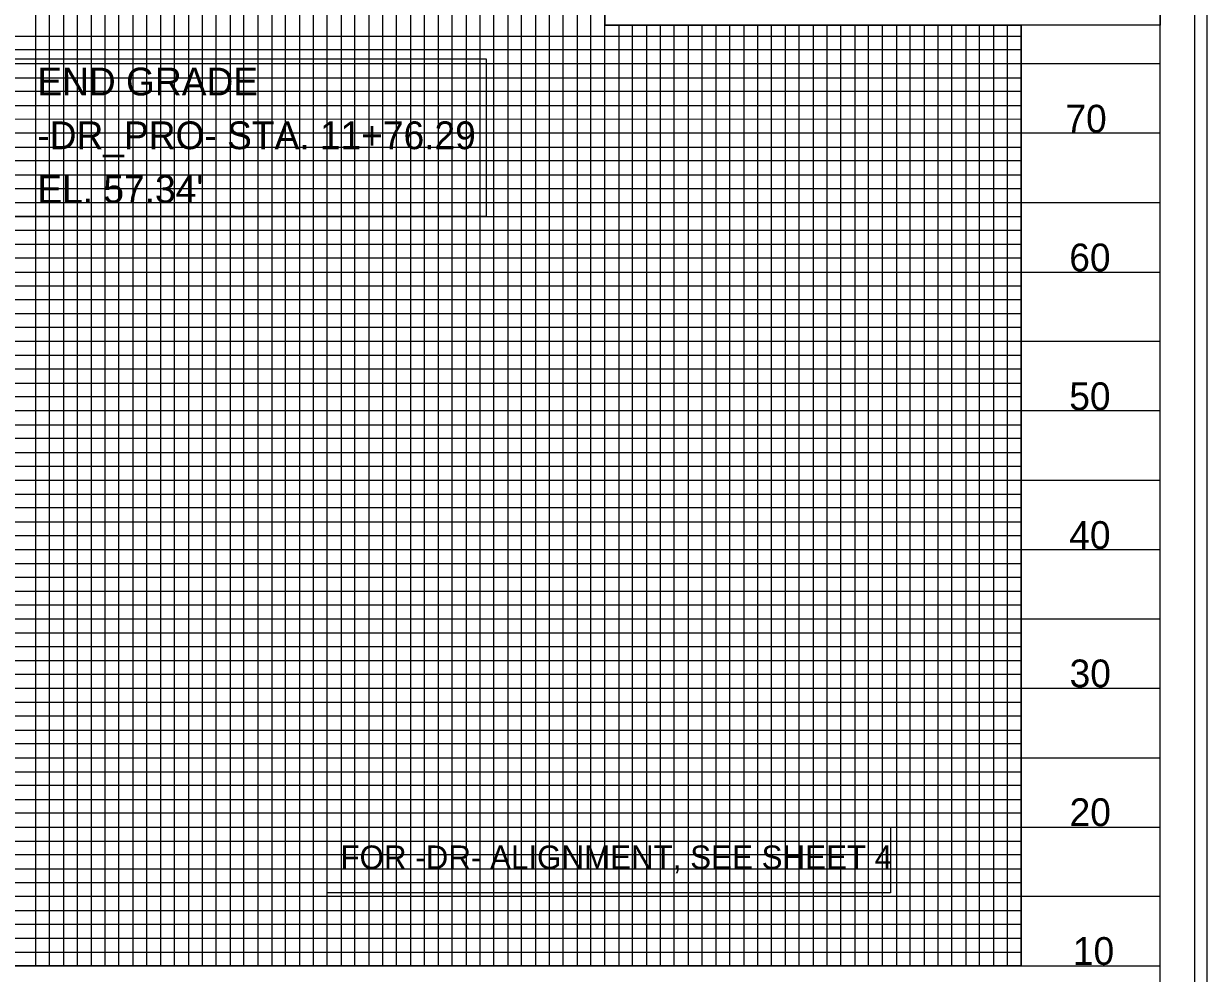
# Model space of a CAD drawing. Extents: x 1019474 to 1021158, y 503201 to 504732.
# Drawn here: x 1020731.9 to 1021158.2, y 503773.1 to 504115.2 of the extents above; entities that cross this region are included whole.
import ezdxf

# ---------------------------------------------------------------- set-up
doc = ezdxf.new("R2010")
doc.units = 0
for name, color, linetype in [('Exist Vertical Profile Vertical Axis Label', 7, 'Continuous'), ('Prop Grid Mask', 7, 'Continuous'), ('Prop Horizontal Alignment Station Label', 7, 'Continuous'), ('Prop Vertical Profile Grade Label', 7, 'Continuous'), ('Scratch_Level_0', 7, 'Continuous'), ('Sheet Layout Profile Border Port 1', 7, 'Continuous'), ('Sheet Layout Profile Border Port 2', 7, 'Continuous'), ('Sheet Plot Border Inside CELL', 7, 'Continuous'), ('Sheet Plot Border Outside CELL', 7, 'Continuous'), ('Sheet Profile CELL', 7, 'Continuous'), ('Sheet Profile Grid Major CELL', 7, 'Continuous'), ('Sheet Profile Grid Middle CELL', 7, 'Continuous'), ('Sheet Profile Grid Minor CELL', 7, 'Continuous'), ('Sheet Sticker Exception Certification CELL', 7, 'Continuous')]:
    doc.layers.add(name, color=color, linetype=linetype)

msp = doc.modelspace()

# ---------------------------------------------------------------- linework, layer by layer
at = {"layer": 'Prop Grid Mask'}
for points in [[(1020725.91, 504102.51), (1020898.5, 504102.51), (1020898.5, 504045.7), (1020725.91, 504045.7)], [(1020841.22, 503825.7), (1021044.05, 503825.7), (1021044.05, 503802), (1020841.22, 503802)]]:
    msp.add_lwpolyline(points, close=True, dxfattribs=at)
at = {"layer": 'Scratch_Level_0'}
msp.add_lwpolyline([(1019691.22, 503775.7), (1019691.22, 504275.7), (1020941.22, 504275.7), (1020941.17, 504114.65), (1021091.22, 504114.65), (1021091.22, 503775.7)], close=True, dxfattribs=at)
at = {"layer": 'Sheet Layout Profile Border Port 1'}
msp.add_lwpolyline([(1019691.22, 504114.65), (1019691.22, 503775.7), (1021091.22, 503775.7), (1021091.22, 504114.65)], dxfattribs=at)
at = {"layer": 'Sheet Layout Profile Border Port 2'}
msp.add_lwpolyline([(1019691.22, 504275.7), (1020941.22, 504275.7), (1020941.17, 504114.65), (1021091.22, 504114.65), (1021091.22, 503775.7), (1019691.22, 503775.7)], close=True, dxfattribs=at)
at = {"layer": 'Sheet Plot Border Inside CELL'}
msp.add_lwpolyline([(1019487.22, 503223.15), (1021153.72, 503223.15), (1021153.72, 504278.25), (1019487.22, 504278.25)], close=True, dxfattribs=at)
at = {"layer": 'Sheet Plot Border Outside CELL'}
msp.add_lwpolyline([(1019474.22, 503200.7), (1021158.22, 503200.7), (1021158.22, 504300.7), (1019474.22, 504300.7)], close=True, dxfattribs=at)
at = {"layer": 'Sheet Profile CELL'}
msp.add_line((1019641.22, 503775.7), (1021141.22, 503775.7), dxfattribs=at)
msp.add_lwpolyline([(1021141.22, 504275.7), (1019641.22, 504275.7), (1019641.22, 503225.7), (1021141.22, 503225.7)], close=True, dxfattribs=at)
at = {"layer": 'Sheet Profile Grid Major CELL'}
for p, q in [((1020741.22, 503775.7), (1020741.22, 504275.7)), ((1020791.22, 504275.7), (1020791.22, 503775.7)), ((1020841.22, 503775.7), (1020841.22, 504275.7)), ((1020891.22, 504275.7), (1020891.22, 503775.7)), ((1020941.22, 503775.7), (1020941.22, 504275.7)), ((1020691.22, 503775.7), (1020741.22, 503775.7)), ((1020791.22, 503775.7), (1020841.22, 503775.7)), ((1020891.22, 503775.7), (1020941.22, 503775.7))]:
    msp.add_line(p, q, dxfattribs=at)
for points in [[(1020991.22, 504114.65), (1020991.22, 503775.7), (1021041.22, 503775.7), (1021041.22, 503775.7), (1021041.22, 504114.65)], [(1021091.22, 504114.65), (1021091.22, 503775.7)], [(1021141.22, 504075.7), (1019641.22, 504075.7), (1019641.22, 504025.7), (1021141.22, 504025.7)], [(1021141.22, 503975.7), (1019641.22, 503975.7), (1019641.22, 503925.7), (1021141.22, 503925.7)], [(1021141.22, 503875.7), (1019641.22, 503875.7), (1019641.22, 503875.7), (1019641.22, 503825.7), (1021141.22, 503825.7)]]:
    msp.add_lwpolyline(points, dxfattribs=at)
at = {"layer": 'Sheet Profile Grid Middle CELL'}
for p, q in [((1020766.22, 503775.7), (1020766.22, 504275.7)), ((1020816.22, 504275.7), (1020816.22, 503775.7)), ((1020866.22, 503775.7), (1020866.22, 504275.7)), ((1020916.22, 504275.7), (1020916.22, 503775.7)), ((1020966.22, 503775.7), (1020966.22, 504114.65)), ((1021016.22, 504114.65), (1021016.22, 503775.7)), ((1021066.22, 503775.7), (1021066.22, 504114.65)), ((1020716.22, 503775.7), (1020766.22, 503775.7)), ((1020816.22, 503775.7), (1020866.22, 503775.7)), ((1020916.22, 503775.7), (1020966.22, 503775.7)), ((1021016.22, 503775.7), (1021066.22, 503775.7))]:
    msp.add_line(p, q, dxfattribs=at)
for points in [[(1021141.22, 504100.7), (1019641.22, 504100.7), (1019641.22, 504050.7), (1021141.22, 504050.7)], [(1021141.22, 504000.7), (1019641.22, 504000.7), (1019641.22, 503950.7), (1021141.22, 503950.7)], [(1021141.22, 503900.7), (1019641.22, 503900.7), (1019641.22, 503850.7), (1021141.22, 503850.7)], [(1021141.22, 503800.7), (1019641.22, 503800.7)]]:
    msp.add_lwpolyline(points, dxfattribs=at)
at = {"layer": 'Sheet Profile Grid Minor CELL'}
for p, q in [((1020836.22, 503775.7), (1020836.22, 504275.7)), ((1020846.22, 504275.7), (1020846.22, 503775.7)), ((1020851.22, 503775.7), (1020851.22, 504275.7)), ((1020856.22, 504275.7), (1020856.22, 503775.7)), ((1020861.22, 503775.7), (1020861.22, 504275.7)), ((1020871.22, 504275.7), (1020871.22, 503775.7)), ((1020876.22, 503775.7), (1020876.22, 504275.7)), ((1020881.22, 504275.7), (1020881.22, 503775.7)), ((1020886.22, 503775.7), (1020886.22, 504275.7)), ((1020896.22, 504275.7), (1020896.22, 503775.7)), ((1020901.22, 503775.7), (1020901.22, 504275.7)), ((1020906.22, 504275.7), (1020906.22, 503775.7)), ((1020911.22, 503775.7), (1020911.22, 504275.7)), ((1020921.22, 504275.7), (1020921.22, 503775.7)), ((1020926.22, 503775.7), (1020926.22, 504275.7)), ((1020931.22, 504275.7), (1020931.22, 503775.7)), ((1020936.22, 503775.7), (1020936.22, 504275.7)), ((1020946.22, 504114.65), (1020946.22, 503775.7)), ((1020951.22, 503775.7), (1020951.22, 504114.65)), ((1020956.22, 504114.65), (1020956.22, 503775.7)), ((1020961.22, 503775.7), (1020961.22, 504114.65)), ((1020971.22, 504114.65), (1020971.22, 503775.7)), ((1020976.22, 503775.7), (1020976.22, 504114.65)), ((1020981.22, 504114.65), (1020981.22, 503775.7)), ((1020986.22, 503775.7), (1020986.22, 504114.65)), ((1020996.22, 504114.65), (1020996.22, 503775.7)), ((1021001.22, 503775.7), (1021001.22, 504114.65)), ((1021006.22, 504114.65), (1021006.22, 503775.7)), ((1021011.22, 503775.7), (1021011.22, 504114.65)), ((1021021.22, 504114.65), (1021021.22, 503775.7)), ((1021026.22, 503775.7), (1021026.22, 504114.65)), ((1021031.22, 504114.65), (1021031.22, 503775.7)), ((1021036.22, 503775.7), (1021036.22, 504114.65)), ((1021046.22, 504114.65), (1021046.22, 503775.7)), ((1021051.22, 503775.7), (1021051.22, 504114.65)), ((1021056.22, 504114.65), (1021056.22, 503775.7)), ((1021061.22, 503775.7), (1021061.22, 504114.65)), ((1021071.22, 504114.65), (1021071.22, 503775.7)), ((1021076.22, 503775.7), (1021076.22, 504114.65)), ((1021081.22, 504114.65), (1021081.22, 503775.7)), ((1021086.22, 503775.7), (1021086.22, 504114.65)), ((1020441.22, 504110.7), (1021091.22, 504110.7)), ((1021091.22, 504105.7), (1020441.22, 504105.7)), ((1020441.22, 504095.7), (1021091.22, 504095.7)), ((1021091.22, 504090.7), (1020441.22, 504090.7)), ((1020441.22, 504085.7), (1021091.22, 504085.7)), ((1021091.22, 504080.7), (1020441.22, 504080.77)), ((1020441.22, 504070.7), (1021091.22, 504070.7)), ((1021091.22, 504065.7), (1020441.22, 504065.7)), ((1020441.22, 504060.7), (1021091.22, 504060.7)), ((1021091.22, 504055.7), (1020441.22, 504055.7)), ((1020441.22, 504045.7), (1021091.22, 504045.7)), ((1021091.22, 504040.7), (1020441.22, 504040.7)), ((1020441.22, 504035.7), (1021091.22, 504035.7)), ((1021091.22, 504030.7), (1020441.22, 504030.7)), ((1020441.22, 504020.7), (1021091.22, 504020.7)), ((1021091.22, 504015.7), (1020441.22, 504015.7)), ((1020441.22, 504010.7), (1021091.22, 504010.7)), ((1021091.22, 504005.7), (1020441.22, 504005.7)), ((1020441.22, 503995.7), (1021091.22, 503995.7)), ((1021091.22, 503990.7), (1020441.22, 503990.7)), ((1020441.22, 503985.7), (1021091.22, 503985.7)), ((1021091.22, 503980.7), (1020441.22, 503980.7)), ((1020441.22, 503970.7), (1021091.22, 503970.7)), ((1021091.22, 503965.7), (1020441.22, 503965.7)), ((1020441.22, 503960.7), (1021091.22, 503960.7)), ((1021091.22, 503955.7), (1020441.22, 503955.7)), ((1020441.22, 503945.7), (1021091.22, 503945.7)), ((1021091.22, 503940.7), (1020441.22, 503940.7)), ((1020441.22, 503935.7), (1021091.22, 503935.7)), ((1021091.22, 503930.7), (1020441.22, 503930.7)), ((1020441.22, 503920.7), (1021091.22, 503920.7)), ((1021091.22, 503915.7), (1020441.22, 503915.7)), ((1020441.22, 503910.7), (1021091.22, 503910.7)), ((1021091.22, 503905.7), (1020441.22, 503905.7)), ((1020441.22, 503895.7), (1021091.22, 503895.7)), ((1021091.22, 503890.7), (1020441.22, 503890.7)), ((1020441.22, 503885.7), (1021091.22, 503885.7)), ((1021091.22, 503880.7), (1020441.22, 503880.7)), ((1020441.22, 503870.7), (1021091.22, 503870.7)), ((1021091.22, 503865.7), (1020441.22, 503865.7)), ((1020441.22, 503860.7), (1021091.22, 503860.7)), ((1021091.22, 503855.7), (1020441.22, 503855.7)), ((1020441.22, 503845.7), (1021091.22, 503845.7)), ((1021091.22, 503840.7), (1020441.22, 503840.7)), ((1020441.22, 503835.7), (1021091.22, 503835.7)), ((1021091.22, 503830.7), (1020441.22, 503830.7)), ((1020441.22, 503820.7), (1021091.22, 503820.7)), ((1021091.22, 503815.7), (1020441.22, 503815.7)), ((1020441.22, 503810.7), (1021091.22, 503810.7)), ((1021091.22, 503805.7), (1020441.22, 503805.7)), ((1020441.22, 503795.7), (1021091.22, 503795.7)), ((1021091.22, 503790.7), (1020441.22, 503790.7)), ((1020441.22, 503785.7), (1021091.22, 503785.7)), ((1020441.22, 503780.7), (1021091.22, 503780.7)), ((1020831.22, 503775.7), (1020836.22, 503775.7)), ((1020846.22, 503775.7), (1020851.22, 503775.7)), ((1020856.22, 503775.7), (1020861.22, 503775.7)), ((1020871.22, 503775.7), (1020876.22, 503775.7)), ((1020881.22, 503775.7), (1020886.22, 503775.7)), ((1020896.22, 503775.7), (1020901.22, 503775.7)), ((1020906.22, 503775.7), (1020911.22, 503775.7)), ((1020921.22, 503775.7), (1020926.22, 503775.7)), ((1020931.22, 503775.7), (1020936.22, 503775.7)), ((1020946.22, 503775.7), (1020951.22, 503775.7)), ((1020956.22, 503775.7), (1020961.22, 503775.7)), ((1020971.22, 503775.7), (1020976.22, 503775.7)), ((1020981.22, 503775.7), (1020986.22, 503775.7)), ((1020996.22, 503775.7), (1021001.22, 503775.7)), ((1021006.22, 503775.7), (1021011.22, 503775.7)), ((1021021.22, 503775.7), (1021026.22, 503775.7)), ((1021031.22, 503775.7), (1021036.22, 503775.7)), ((1021046.22, 503775.7), (1021051.22, 503775.7)), ((1021056.22, 503775.7), (1021061.22, 503775.7)), ((1021071.22, 503775.7), (1021076.22, 503775.7)), ((1021081.22, 503775.7), (1021086.22, 503775.7))]:
    msp.add_line(p, q, dxfattribs=at)
for points in [[(1020731.22, 503775.7), (1020736.22, 503775.7), (1020736.22, 504275.7)], [(1020746.22, 504275.7), (1020746.22, 503775.7), (1020751.22, 503775.7), (1020751.22, 504275.7)], [(1020756.22, 504275.7), (1020756.22, 503775.7), (1020761.22, 503775.7), (1020761.22, 504275.7)], [(1020771.22, 504275.7), (1020771.22, 503775.7), (1020776.22, 503775.7), (1020776.22, 504275.7)], [(1020781.22, 504275.7), (1020781.22, 503775.7), (1020786.22, 503775.7), (1020786.22, 504275.7)], [(1020796.22, 504275.7), (1020796.22, 503775.7), (1020801.22, 503775.7), (1020801.22, 504275.7)], [(1020806.22, 504275.7), (1020806.22, 503775.7), (1020811.22, 503775.7), (1020811.22, 504275.7)], [(1020821.22, 504275.7), (1020821.22, 503775.7), (1020826.22, 503775.7), (1020826.22, 504275.7)], [(1020831.22, 504275.7), (1020831.22, 503775.7)]]:
    msp.add_lwpolyline(points, dxfattribs=at)
at = {"layer": 'Sheet Sticker Exception Certification CELL'}
for p, q in [((1020941.17, 504114.65), (1020941.17, 504138.15)), ((1020941.17, 504114.65), (1020941.17, 504138.15)), ((1021141.21, 504138.13), (1021141.21, 504114.63)), ((1021141.21, 504138.13), (1021141.21, 504114.63)), ((1021141.21, 504114.65), (1020941.17, 504114.65)), ((1021141.21, 504114.65), (1020941.17, 504114.65))]:
    msp.add_line(p, q, dxfattribs=at)

# ---------------------------------------------------------------- texts
at = {"layer": 'Exist Vertical Profile Vertical Axis Label'}
for s, p in [('70', (1021107.11, 504075.95)), ('60', (1021108.49, 504025.95)), ('50', (1021108.49, 503975.95)), ('40', (1021108.49, 503925.95)), ('30', (1021108.61, 503876.1)), ('20', (1021108.61, 503826.1)), ('10', (1021109.8, 503776.1))]:
    msp.add_text(s, height=10, dxfattribs=at).set_placement(p)
at = {"layer": 'Prop Horizontal Alignment Station Label'}
msp.add_text('FOR -DR- ALIGNMENT, SEE SHEET 4', height=8.4375, dxfattribs=at).set_placement((1020845.98, 503810.67))
at = {"layer": 'Prop Vertical Profile Grade Label'}
for s, p in [('END GRADE', (1020736.81, 504089.33)), ('-DR_PRO- STA. 11+76.29', (1020736.81, 504069.96)), ("EL. 57.34'", (1020736.81, 504050.58))]:
    msp.add_text(s, height=10, rotation=360, dxfattribs=at).set_placement(p)

doc.saveas('drawing.dxf')
